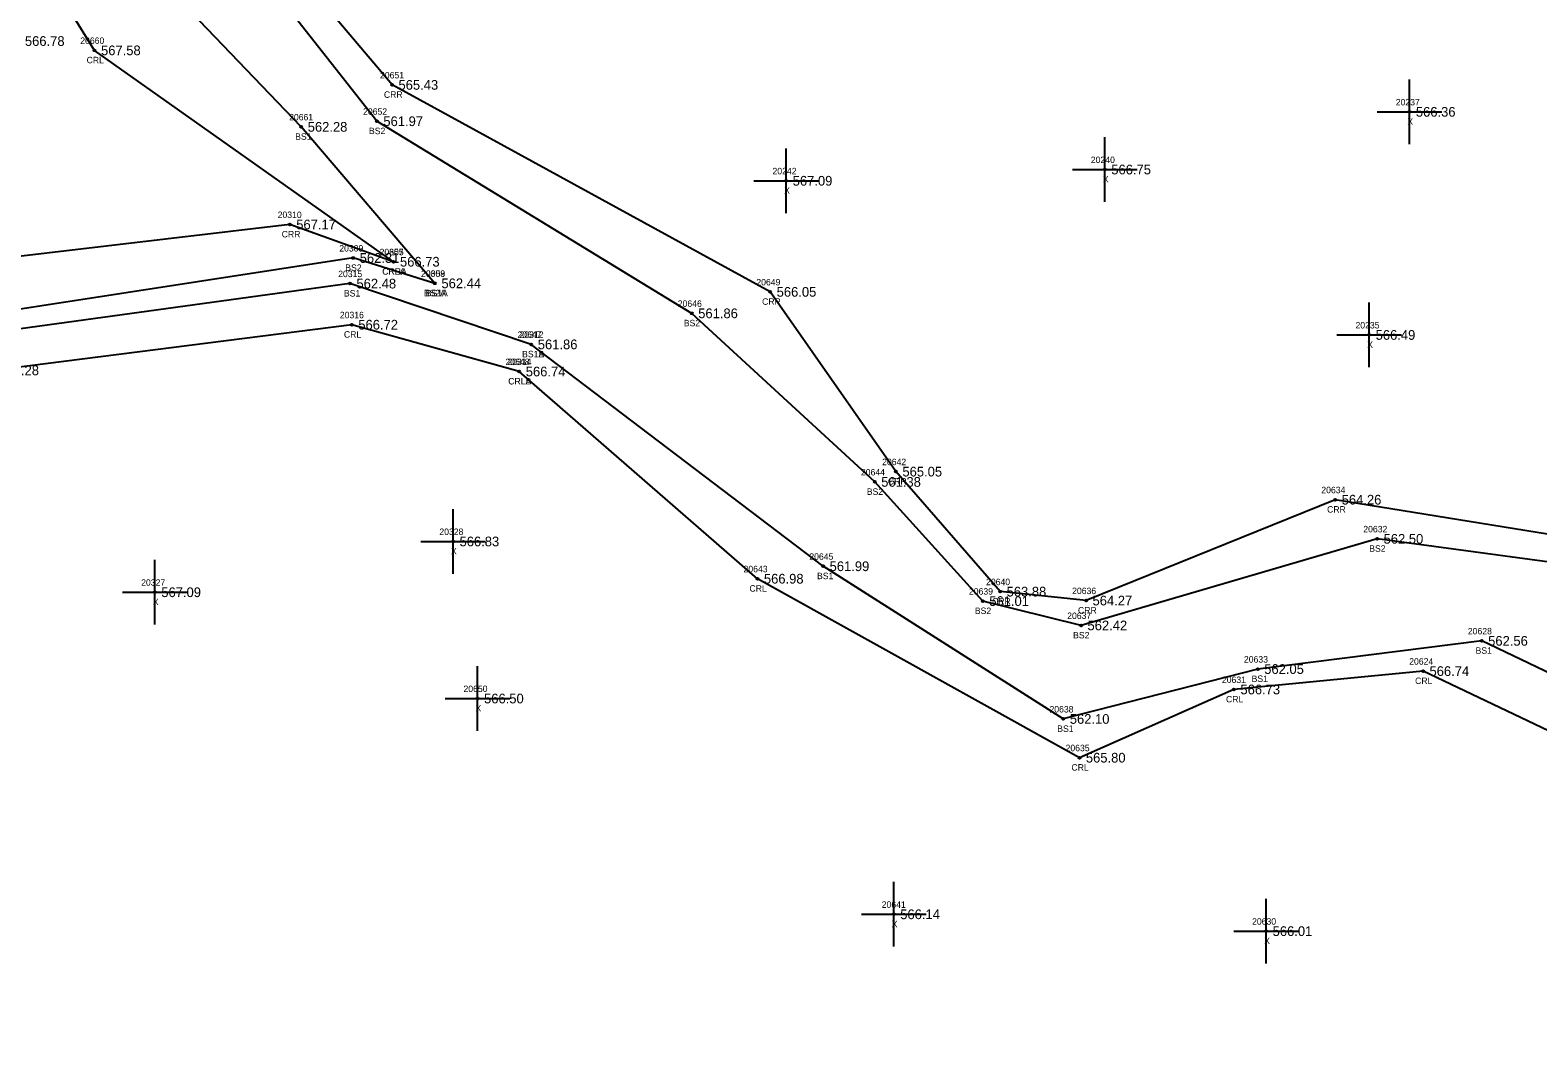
# Model space of a CAD drawing. Extents: x 1530159 to 1531652, y 877045 to 877724.
# Drawn here: x 1530915.9 to 1531149.1, y 877076.5 to 877232.3 of the extents above; entities that cross this region are included whole.
import ezdxf

# ---------------------------------------------------------------- set-up
doc = ezdxf.new("R2010")
doc.units = 0
for name, color, linetype in [('RD_DTM_BkLn2', 7, 'Continuous'), ('RD_DTM_BkLn_txCode', 7, 'Continuous'), ('RD_EX_H2O', 7, 'Continuous'), ('RD_EX_H2O_txCode', 7, 'Continuous'), ('RD_EX_Misc', 7, 'Continuous'), ('RD_EX_Misc_txCode', 7, 'Continuous'), ('RD_EX_TX_H2O_ELEV', 7, 'Continuous'), ('RD_EX_TX_Misc_ELEV', 7, 'Continuous'), ('RD_SMD_Locator', 7, 'Continuous')]:
    doc.layers.add(name, color=color, linetype=linetype)

msp = doc.modelspace()

# ---------------------------------------------------------------- linework, layer by layer
at = {"layer": 'RD_DTM_BkLn2'}
for points in [[(1530978.51, 877193.14), (1530957.83, 877217.34), (1530939.69, 877236.27), (1530919.92, 877243.6), (1530901.7, 877240.19), (1530890.91, 877253.72), (1530883.61, 877289.66), (1530871.34, 877309.06), (1530854.23, 877336.62), (1530832.44, 877361.15), (1530819.05, 877374.38), (1530808.85, 877385.69), (1530794.67, 877405.25), (1530798.76, 877416.08), (1530761.4, 877471.05), (1530729.88, 877527.47), (1530702.64, 877561.57), (1530689.57, 877599.12), (1530672.36, 877642.36), (1530634.08, 877679.71), (1530613.02, 877709.76)], [(1531348.08, 877109.37), (1531329.65, 877115.18), (1531326.16, 877131.65), (1531301.87, 877132.06), (1531267.22, 877105.63), (1531250.04, 877095.06), (1531235.2, 877094.62), (1531224.6, 877103.25), (1531205.62, 877122.91), (1531190.69, 877134.41), (1531175.3, 877135.54), (1531152.78, 877149.76), (1531124.21, 877153.63), (1531078.42, 877140.23), (1531063.23, 877144), (1531046.52, 877162.43), (1531018.22, 877188.5), (1530969.53, 877218.21), (1530954.08, 877237.92), (1530933.73, 877250.44), (1530924.53, 877258.32), (1530897.88, 877293.87)], [(1530978.51, 877193.14), (1530965.87, 877197.06), (1530905.97, 877187.85), (1530887.44, 877189.29), (1530869.35, 877180.17)], [(1530993.41, 877183.7), (1530965.37, 877193.1), (1530907.25, 877185.15), (1530889.71, 877184.65), (1530872.17, 877176.49)], [(1531350.94, 877092.41), (1531319.5, 877105.67), (1531308.68, 877114.9), (1531312.97, 877122.15), (1531275.99, 877094.29), (1531246.82, 877079.52), (1531214.83, 877095.33), (1531195.48, 877111.64), (1531156.11, 877130.34), (1531140.38, 877137.85), (1531105.75, 877133.49), (1531075.68, 877125.77), (1531038.54, 877149.39), (1530993.41, 877183.7)]]:
    msp.add_lwpolyline(points, dxfattribs=at)
at = {"layer": 'RD_EX_H2O'}
for points in [[(1530972.1, 877196.48), (1530925.87, 877229.17), (1530918.34, 877241.35), (1530897.53, 877235.99), (1530881.25, 877248.19), (1530880.72, 877258.4), (1530879.1, 877290.18), (1530865.94, 877309.23), (1530832.49, 877347.64), (1530816.44, 877373.18)], [(1531348.73, 877112.8), (1531330.35, 877118.79), (1531327.02, 877134.75), (1531298.38, 877136.98), (1531263.7, 877109.21), (1531249.44, 877098.17), (1531237.97, 877099.69), (1531227.95, 877107.18), (1531213.47, 877126.62), (1531190.85, 877137.63), (1531178.72, 877139.79), (1531157.55, 877153.22), (1531117.73, 877159.68), (1531079.2, 877144.08), (1531065.91, 877145.46), (1531049.8, 877164.02), (1531030.35, 877191.82), (1530971.87, 877223.83), (1530957.12, 877241.36), (1530927.2, 877260.93), (1530922.5, 877289.86), (1530895.04, 877301.24)], [(1530972.1, 877196.48), (1530956.06, 877202.24), (1530899.21, 877195.52), (1530866.11, 877186.01), (1530871.9, 877170.1)], [(1530991.55, 877179.5), (1530965.66, 877186.74), (1530910.14, 877179.68), (1530871.9, 877170.1)], [(1531352.2, 877088.06), (1531314.99, 877102.13), (1531274.47, 877089.9), (1531245.67, 877076.46), (1531215.61, 877089.16), (1531183.19, 877108.46), (1531131.31, 877133.17), (1531102.07, 877130.33), (1531078.17, 877119.78), (1531028.38, 877147.46), (1530991.55, 877179.5)]]:
    msp.add_lwpolyline(points, dxfattribs=at)
at = {"layer": 'RD_EX_Misc'}
for p, q in [((1531129.2, 877214.66), (1531129.2, 877224.66)), ((1531124.2, 877219.66), (1531134.2, 877219.66)), ((1531032.83, 877204), (1531032.83, 877214)), ((1531082.1, 877205.74), (1531082.1, 877215.74)), ((1531077.1, 877210.74), (1531087.1, 877210.74)), ((1531027.83, 877209), (1531037.83, 877209)), ((1531122.98, 877180.16), (1531122.98, 877190.16)), ((1531117.98, 877185.16), (1531127.98, 877185.16)), ((1530981.31, 877148.22), (1530981.31, 877158.22)), ((1530976.31, 877153.22), (1530986.31, 877153.22)), ((1530935.19, 877140.37), (1530935.19, 877150.37)), ((1530930.19, 877145.37), (1530940.19, 877145.37)), ((1530985.1, 877123.93), (1530985.1, 877133.93)), ((1530980.1, 877128.93), (1530990.1, 877128.93)), ((1531049.46, 877090.56), (1531049.46, 877100.56)), ((1531107.05, 877087.96), (1531107.05, 877097.96)), ((1531044.46, 877095.56), (1531054.46, 877095.56)), ((1531102.05, 877092.96), (1531112.05, 877092.96))]:
    msp.add_line(p, q, dxfattribs=at)
at = {"layer": 'RD_SMD_Locator'}
for centre in [(1530925.87, 877229.17), (1530971.87, 877223.83), (1530969.53, 877218.21), (1531129.2, 877219.66), (1530957.83, 877217.34), (1531032.83, 877209), (1531082.1, 877210.74), (1530956.06, 877202.24), (1530965.87, 877197.06), (1530972.1, 877196.48), (1530972.1, 877196.48), (1530965.37, 877193.1), (1530978.51, 877193.14), (1530978.51, 877193.14), (1531030.35, 877191.82), (1531018.22, 877188.5), (1530965.66, 877186.74), (1530993.41, 877183.7), (1530993.41, 877183.7), (1531122.98, 877185.16), (1530991.55, 877179.5), (1530991.55, 877179.5), (1531046.52, 877162.43), (1531049.8, 877164.02), (1531117.73, 877159.68), (1530981.31, 877153.22), (1531124.21, 877153.63), (1531038.54, 877149.39), (1531028.38, 877147.46), (1530935.19, 877145.37), (1531063.23, 877144), (1531065.91, 877145.46), (1531079.2, 877144.08), (1531078.42, 877140.23), (1531140.38, 877137.85), (1531105.75, 877133.49), (1531131.31, 877133.17), (1531102.07, 877130.33), (1530985.1, 877128.93), (1531075.68, 877125.77), (1531078.17, 877119.78), (1531049.46, 877095.56), (1531107.05, 877092.96)]:
    msp.add_circle(centre, 0.15, dxfattribs=at)

# ---------------------------------------------------------------- texts
at = {"layer": 'RD_DTM_BkLn_txCode'}
for s, p in [('20661', (1530955.95, 877218.34)), ('20652', (1530967.39, 877219.21)), ('BS1', (1530956.89, 877215.34)), ('BS2', (1530968.3, 877216.21)), ('20309', (1530963.71, 877198.06)), ('20315', (1530963.54, 877194.1)), ('BS2', (1530964.64, 877195.06)), ('20308', (1530976.35, 877194.14)), ('20659', (1530976.37, 877194.14)), ('BS1', (1530964.43, 877191.1)), ('BS2A', (1530976.79, 877191.14)), ('BS1A', (1530977.08, 877191.14)), ('20646', (1531016.06, 877189.5)), ('20647', (1530991.27, 877184.7)), ('20312', (1530991.58, 877184.7)), ('BS2', (1531016.99, 877186.5)), ('BS1A', (1530991.98, 877181.7)), ('BS1B', (1530991.99, 877181.7)), ('20644', (1531044.38, 877163.43)), ('BS2', (1531045.29, 877160.43)), ('20632', (1531122.07, 877154.63)), ('20645', (1531036.4, 877150.39)), ('BS2', (1531122.99, 877151.63)), ('BS1', (1531037.59, 877147.39)), ('20639', (1531061.09, 877145)), ('BS2', (1531062, 877142)), ('20637', (1531076.28, 877141.23)), ('BS2', (1531077.19, 877138.23)), ('20628', (1531138.24, 877138.85)), ('BS1', (1531139.43, 877135.85)), ('20633', (1531103.61, 877134.49)), ('BS1', (1531104.8, 877131.49)), ('20638', (1531073.54, 877126.77)), ('BS1', (1531074.74, 877123.77))]:
    msp.add_text(s, height=1, dxfattribs=at).set_placement(p)
at = {"layer": 'RD_EX_H2O_txCode'}
for s, p in [('20660', (1530923.66, 877230.17)), ('CRL', (1530924.64, 877227.17)), ('20651', (1530970.01, 877224.83)), ('CRR', (1530970.62, 877221.83)), ('20310', (1530954.18, 877203.24)), ('CRR', (1530954.81, 877200.24)), ('20307', (1530969.94, 877197.48)), ('20655', (1530969.95, 877197.48)), ('CRRA', (1530970.35, 877194.48)), ('CRLA', (1530970.38, 877194.48)), ('20649', (1531028.21, 877192.82)), ('CRR', (1531029.1, 877189.82)), ('20316', (1530963.8, 877187.74)), ('CRL', (1530964.43, 877184.74)), ('20648', (1530989.41, 877180.5)), ('20314', (1530989.71, 877180.5)), ('CRLA', (1530989.83, 877177.5)), ('CRLB', (1530989.85, 877177.5)), ('20642', (1531047.66, 877165.02)), ('CRR', (1531048.55, 877162.02)), ('20634', (1531115.58, 877160.68)), ('CRR', (1531116.47, 877157.68)), ('20643', (1531026.23, 877148.46)), ('CRL', (1531027.15, 877145.46)), ('20640', (1531063.73, 877146.46)), ('20636', (1531077.04, 877145.08)), ('CRR', (1531064.66, 877143.46)), ('CRR', (1531077.95, 877142.08)), ('20624', (1531129.17, 877134.17)), ('20631', (1531100.21, 877131.33)), ('CRL', (1531130.08, 877131.17)), ('CRL', (1531100.84, 877128.33)), ('20635', (1531076.03, 877120.78)), ('CRL', (1531076.94, 877117.78))]:
    msp.add_text(s, height=1, dxfattribs=at).set_placement(p)
at = {"layer": 'RD_EX_Misc_txCode'}
for s, p in [('20237', (1531127.09, 877220.66)), ('X', (1531128.89, 877217.66)), ('20240', (1531079.94, 877211.74)), ('20242', (1531030.71, 877210)), ('X', (1531081.79, 877208.74)), ('X', (1531032.51, 877207)), ('20235', (1531120.86, 877186.16)), ('X', (1531122.67, 877183.16)), ('20328', (1530979.19, 877154.22)), ('X', (1530980.99, 877151.22)), ('20327', (1530933.08, 877146.37)), ('X', (1530934.88, 877143.37)), ('20650', (1530982.92, 877129.93)), ('X', (1530984.78, 877126.93)), ('20641', (1531047.6, 877096.56)), ('20630', (1531104.87, 877093.96)), ('X', (1531049.14, 877093.56)), ('X', (1531106.74, 877090.96))]:
    msp.add_text(s, height=1, dxfattribs=at).set_placement(p)
at = {"layer": 'RD_EX_TX_H2O_ELEV'}
for s, p in [('567.58', (1530926.87, 877228.42)), ('565.43', (1530972.87, 877223.08)), ('567.17', (1530957.06, 877201.49)), ('566.73', (1530973.1, 877195.73)), ('566.73', (1530973.1, 877195.73)), ('566.05', (1531031.35, 877191.07)), ('566.72', (1530966.66, 877185.99)), ('567.28', (1530911.14, 877178.93)), ('566.74', (1530992.55, 877178.75)), ('566.74', (1530992.55, 877178.75)), ('565.05', (1531050.8, 877163.27)), ('564.26', (1531118.73, 877158.93)), ('566.98', (1531029.38, 877146.71)), ('563.88', (1531066.91, 877144.71)), ('564.27', (1531080.2, 877143.33)), ('566.74', (1531132.31, 877132.42)), ('566.73', (1531103.07, 877129.58)), ('565.80', (1531079.17, 877119.03))]:
    msp.add_text(s, height=1.5, dxfattribs=at).set_placement(p)
at = {"layer": 'RD_EX_TX_Misc_ELEV'}
for s, p in [('566.78', (1530915.1, 877229.86)), ('561.97', (1530970.53, 877217.46)), ('566.36', (1531130.2, 877218.91)), ('562.28', (1530958.83, 877216.59)), ('566.75', (1531083.1, 877209.99)), ('567.09', (1531033.83, 877208.25)), ('562.31', (1530966.87, 877196.31)), ('562.48', (1530966.37, 877192.35)), ('562.44', (1530979.51, 877192.39)), ('562.44', (1530979.51, 877192.39)), ('561.86', (1531019.22, 877187.75)), ('566.49', (1531123.98, 877184.41)), ('561.86', (1530994.41, 877182.95)), ('561.86', (1530994.41, 877182.95)), ('561.38', (1531047.52, 877161.68)), ('566.83', (1530982.31, 877152.47)), ('562.50', (1531125.21, 877152.88)), ('561.99', (1531039.54, 877148.64)), ('567.09', (1530936.19, 877144.62)), ('561.01', (1531064.23, 877143.25)), ('562.42', (1531079.42, 877139.48)), ('562.56', (1531141.38, 877137.1)), ('562.05', (1531106.75, 877132.74)), ('566.50', (1530986.1, 877128.18)), ('562.10', (1531076.68, 877125.02)), ('566.14', (1531050.46, 877094.81)), ('566.01', (1531108.05, 877092.21))]:
    msp.add_text(s, height=1.5, dxfattribs=at).set_placement(p)

doc.saveas('drawing.dxf')
